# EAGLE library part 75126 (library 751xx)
75xxx DEVICE
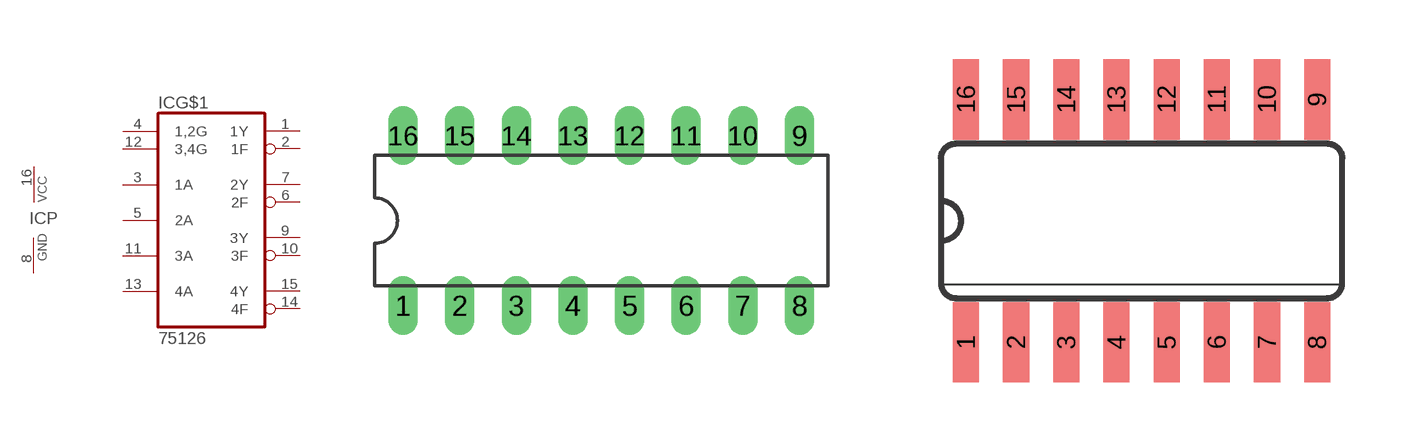
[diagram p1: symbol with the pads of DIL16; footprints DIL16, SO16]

Designator prefix IC; gates G$1=75126 P=PWRN

## 75126P  [DIL16]
1  G$1:1Y  out
2  G$1:1F  out
3  G$1:1A  in
4  G$1:1,2G  in
5  G$1:2A  in
6  G$1:2F  out
7  G$1:2Y  out
8  P:GND  pwr
9  G$1:3Y  out
10  G$1:3F  out
11  G$1:3A  in
12  G$1:3,4G  in
13  G$1:4A  in
14  G$1:4F  out
15  G$1:4Y  out
16  P:VCC  pwr

## 75126SO  [SO16]
Pads as for DIL16

## Footprint DIL16 (pad centres in mm)
Dual In Line Package
drill 0.813 long: 1 -8.89,-3.81; 2 -6.35,-3.81; 3 -3.81,-3.81; 4 -1.27,-3.81; 5 1.27,-3.81; 6 3.81,-3.81; 7 6.35,-3.81; 8 8.89,-3.81; 9 8.89,3.81; 10 6.35,3.81; 11 3.81,3.81; 12 1.27,3.81; 13 -1.27,3.81; 14 -3.81,3.81; 15 -6.35,3.81; 16 -8.89,3.81

## Footprint SO16 (pad centres in mm)
Small Outline package 150 mil
smd 0.66 x 2.032: 1 -4.445,-3.073; 2 -3.175,-3.073; 3 -1.905,-3.073; 4 -0.635,-3.073; 5 0.635,-3.073; 6 1.905,-3.073; 7 3.175,-3.073; 8 4.445,-3.073; 9 4.445,3.073; 10 3.175,3.073; 11 1.905,3.073; 12 0.635,3.073; 13 -0.635,3.073; 14 -1.905,3.073; 15 -3.175,3.073; 16 -4.445,3.073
